(* Logix 5000 project; controller DF1_Sample 1756-L63 rev 19.52; software revision 19.01 *)

TASK MainTask (continuous, watchdog 500 ms) : MainProgram

MODULES
   Local : 1756-L63 (ICP 0, rev 19.52)
      EN2T_102 : 1756-EN2T (ICP 1, Ethernet 192.168.0.102, rev 1.3)
         PLX51DF1ENI : ETHERNET-MODULE (Ethernet 192.168.0.229, rev 1.1, Output RPI 500 ms)
END_MODULES

TYPE PLX51DF1Input :
STRUCT
   Instance : STRING;
   Status : PLX51DF1Status;
   TransactionRate : DINT;   // The transaction rate is the number of DF1 messages per second that the module is routing
   Temperature : REAL;   // The internal temperature of the module
   DF1RxPacketCount : DINT;   // The number of DF1 packets received by the module
   DF1TxPacketCount : DINT;   // The number of DF1 packets sent by the module
   DF1ChecksumErrors : DINT;   // The number of corrupted DF1 packets received by the module
   PCCCRequests : DINT;   // The number of Ethernet/IP PCCC request sent
   PCCCFailures : DINT;   // The number of failed Ethernet/IP PCCC responses received by the module
   TagReads : DINT;   // The total number of tags reads executed by the module
   TagWrites : DINT;   // The total number of tags writes executed by the module
   TagConnectionFailures : DINT;   // The number of failed class 3 connection attempts
   TagErrors : DINT;   // The number of failed tag access (read/write) requests
END_STRUCT
END_TYPE

TYPE PLX51DF1RMsgDataType :
STRUCT
   BOOLEAN : BOOL;
   INT : BOOL;
   REAL : BOOL;
END_STRUCT
END_TYPE

TYPE PLX51DF1RMsgFunctionType :
STRUCT
   PLC5TypedRead : BOOL;
   PLC5TypedWrite : BOOL;
   SLCTypedRead : BOOL;
   SLCTypedWrite : BOOL;
END_STRUCT
END_TYPE

TYPE PLX51DF1RMsgRequest :   // Message Request Parameters
STRUCT
   DestinationNode : INT;
   DF1DataFileAddress : STRING;
   Function : PLX51DF1RMsgFunctionType;
   DataType : PLX51DF1RMsgDataType;
   ElementCount : INT;
   RequestData : INT[128];
END_STRUCT
END_TYPE

TYPE PLX51DF1RMsgResponse :   // Message Response
STRUCT
   Status : INT;
   ResponseLength : INT;
   ResponseData : INT[128];
END_STRUCT
END_TYPE

TYPE PLX51DF1ROutput :   // This parameter is used for the Output Assembly
STRUCT
   RoutingInhibit : BOOL;
END_STRUCT
END_TYPE

TYPE PLX51DF1Status :   // This section reflects the status of the unit
STRUCT
   BridgeMode : BOOL;
   DF1SlaveMode : BOOL;
   ScheduledMode : BOOL;
   UnscheduledMode : BOOL;
   ConfigurationValid : BOOL;
   RoutingInhibited : BOOL;
   Reserved0 : BOOL;
   Reserved1 : BOOL;
   ScheduledTagStatus0 : BOOL;
   ScheduledTagStatus1 : BOOL;
   ScheduledTagStatus2 : BOOL;
   ScheduledTagStatus3 : BOOL;
   ScheduledTagStatus4 : BOOL;
   ScheduledTagStatus5 : BOOL;
   ScheduledTagStatus6 : BOOL;
   ScheduledTagStatus7 : BOOL;
   ScheduledTagStatus8 : BOOL;
   ScheduledTagStatus9 : BOOL;
   ScheduledTagStatus10 : BOOL;
   ScheduledTagStatus11 : BOOL;
   ScheduledTagStatus12 : BOOL;
   ScheduledTagStatus13 : BOOL;
   ScheduledTagStatus14 : BOOL;
   ScheduledTagStatus15 : BOOL;
   ScheduledTagStatus16 : BOOL;
   ScheduledTagStatus17 : BOOL;
   ScheduledTagStatus18 : BOOL;
   ScheduledTagStatus19 : BOOL;
END_STRUCT
END_TYPE

VAR_GLOBAL   (* controller tags *)
   DataToSLC : INT[20];
   PLX51DF1Input : PLX51DF1Input := (Instance := 'DF1 Router', Status.DF1SlaveMode := 1, Status.ConfigurationValid := 1);
   PLX51DF1Message : MESSAGE;
        MessageParameters(ServiceCode := 16#006a, LocalElement := PLX51DF1RMsgRequest, DestinationTag := PLX51DF1MsgResponse, ...)
   PLX51DF1MsgResponse : PLX51DF1RMsgResponse;
   PLX51DF1MsgTrigger : BOOL;   // Message Trigger
   PLX51DF1Output : PLX51DF1ROutput;
   PLX51DF1RMsgRequest : PLX51DF1RMsgRequest := (DestinationNode := 5, DF1DataFileAddress := 'N10:0', Function.PLC5TypedRead := 1, DataType.INT := 1, ElementCount := 16);
END_VAR

PROGRAM MainProgram   (* main routine MainRoutine *)

ROUTINE MainRoutine   (* ladder *)
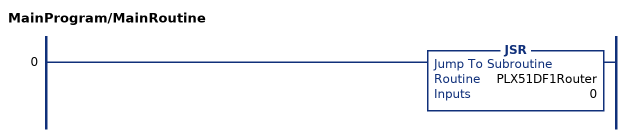
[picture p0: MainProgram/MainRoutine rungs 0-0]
   0: JSR(PLX51DF1Router,0);
END_ROUTINE

ROUTINE PLX51DF1Router   (* ladder *)
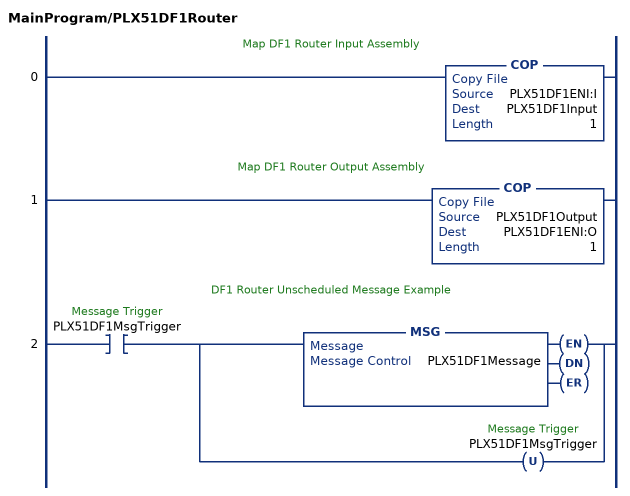
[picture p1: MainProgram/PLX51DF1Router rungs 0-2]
   // Map DF1 Router Input Assembly
   0: COP(PLX51DF1ENI:I,PLX51DF1Input,1);
   // Map DF1 Router Output Assembly
   1: COP(PLX51DF1Output,PLX51DF1ENI:O,1);
   // DF1 Router Unscheduled Message Example
   2: XIC(PLX51DF1MsgTrigger)[MSG(PLX51DF1Message) ,OTU(PLX51DF1MsgTrigger) ];
END_ROUTINE
END_PROGRAM
